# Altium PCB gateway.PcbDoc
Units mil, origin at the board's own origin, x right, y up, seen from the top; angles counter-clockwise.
Board outline 6000 x 4000 mil, 2 copper layers (Top Layer, Bottom Layer); 114 components, 94 nets, 405 pads, 209 vias.
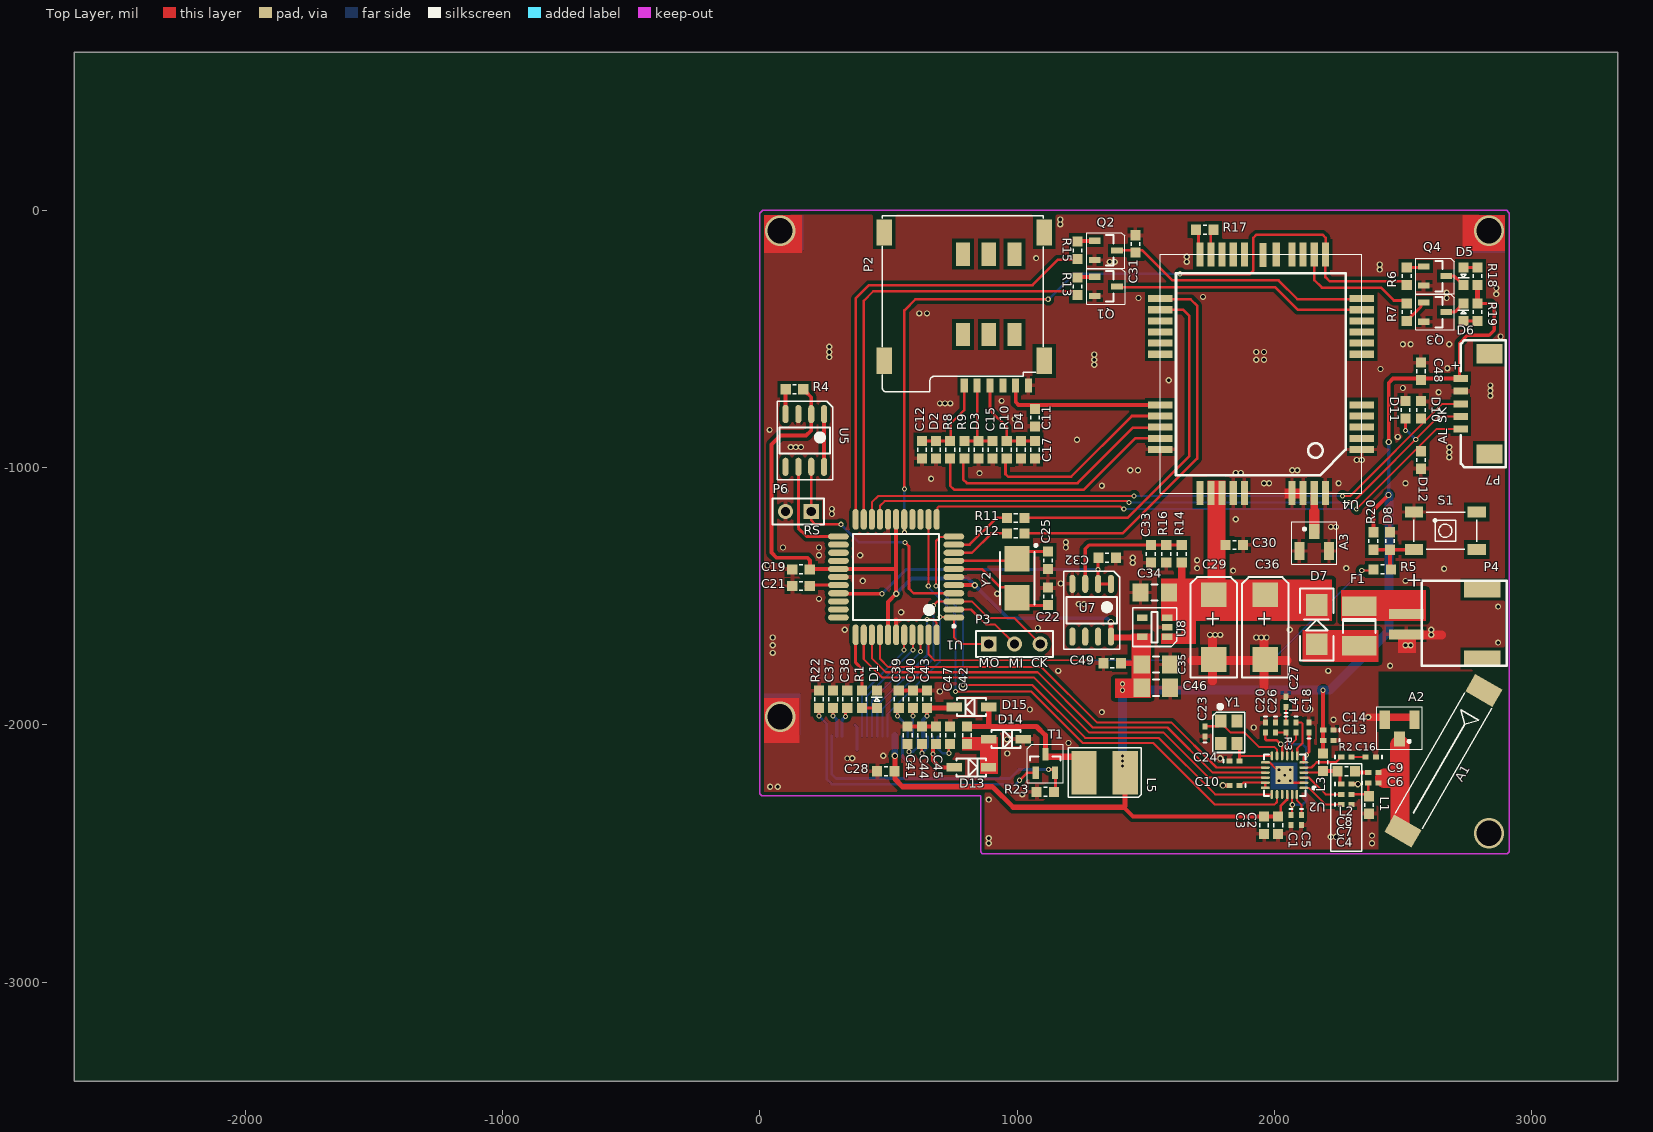
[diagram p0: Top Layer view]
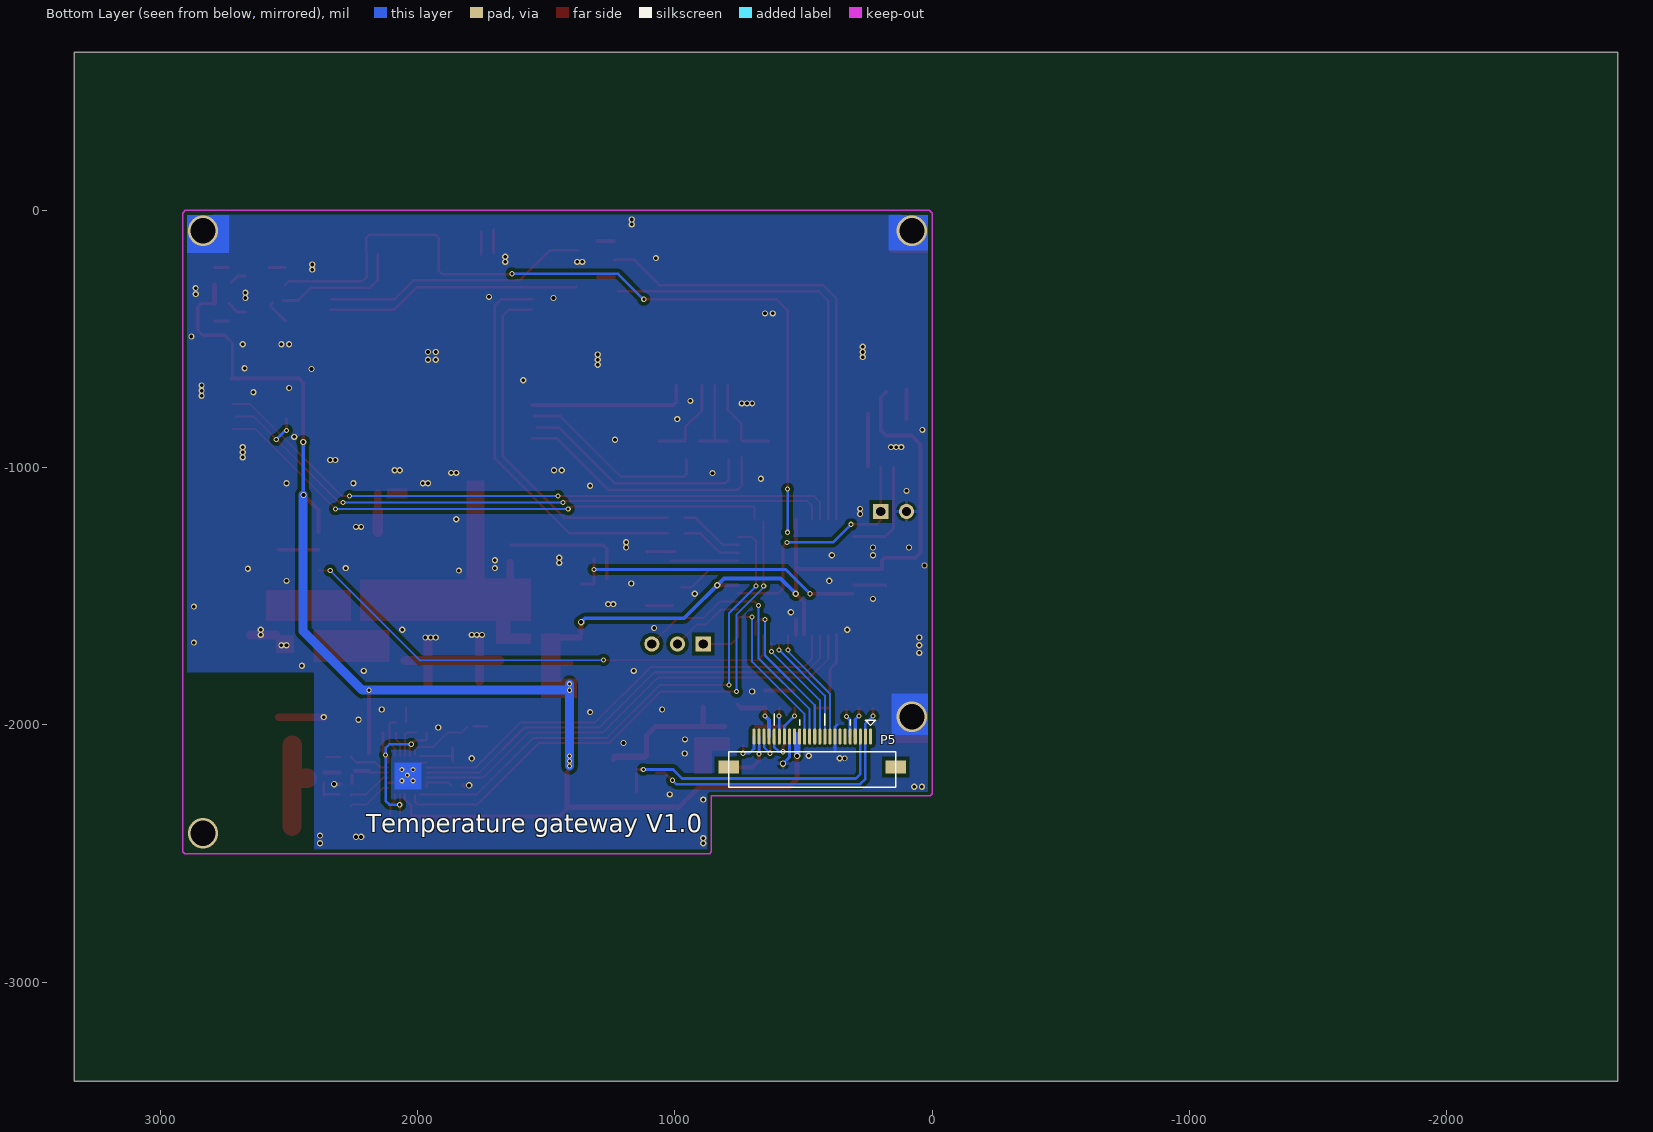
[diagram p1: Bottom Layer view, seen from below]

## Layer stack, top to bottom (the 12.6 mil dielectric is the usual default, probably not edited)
Top Layer: signal copper 1.4
Dielectric: dielectric 12.6, FR-4, Dk 4.8
Bottom Layer: signal copper 1.4

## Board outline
-2665,-3385 3335,-3385 3335,615 -2665,615

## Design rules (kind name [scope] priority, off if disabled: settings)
Clearance [All] p1 off: gap=12
ComponentClearance [All] p1 off: gap=10 collisioncheckmode=3 verticalgap=10
HoleSize [All] p1: absolutevalues=TRUE maxlimit=200 minlimit=1 maxpercent=80.000 minpercent=20.000
PolygonConnect [All] p1: connectstyle=Relief reliefconductorwidth=15 reliefentries=4 polygonreliefangle="90 Angle"
RoutingVias [All] p1: holewidth=28 width=50 viastyle="Through Hole" minholewidth=10 minwidth=20 maxholewidth=200 maxwidth=300
SolderMaskExpansion [All] p1: expansion=4
TestPointUsage [All] p1: valid=0 allowmultiple=FALSE
Testpoint [(IsPad And (OnTopLayer Or OnBottomLayer))] p1: side=3 testpointundercomponent=TRUE minsize=40 maxsize=100 preferedsize=60 minholesize=0 maxholesize=40 preferedholesize=32 testpointgrid=1 style=297 order=0123456789
Width [All] p1: maxlimit=200 minlimit=8 preferedwidth=10 toplayer_prefwidth=12 bottomlayer_prefwidth=12 minimp=50.000000 maximp=50.000000 favimp=50.000000
17 further rules are at their usual default settings.

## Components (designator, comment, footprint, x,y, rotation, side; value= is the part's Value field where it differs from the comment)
A1 "ANTA" ANTA-433 2500,-2412 r60 top
A2 "ANTA" IPEX 2487,-2008 r270 top
A3 "IPEX" IPEX 2155,-1295 r90 top
C1 "Cap" 0402-A 2065,-2370 r270 top
C2 "Cap" 0603 2015,-2390 r270 top
C3 "Cap" 0603 1960,-2390 r270 top
C4 "Cap" 0402-A 2280,-2310 r0 top
C5 "Cap" 0402-A 2105,-2370 r270 top
C6 "Cap" 0402-A 2385,-2225 r0 top
C7 "Cap" 0402-A 2280,-2270 r0 top
C8 "Cap" 0402-A 2280,-2230 r0 top
C9 "Cap" 0402-A 2385,-2185 r0 top
C10 "Cap" 0402-A 1845,-2235 r180 top
C11 "Cap" 0603 1070,-805 r90 top
C12 "Cap" 0603 630,-930 r90 top
C13 "Cap" 0402-A 2210,-2060 r180 top
C14 "Cap" 0402-A 2210,-2020 r180 top
C15 "Cap" 0603 905,-930 r270 top
C16 "Cap" 0402-A 2375,-2125 r180 top
C17 "Cap" 0603 1070,-930 r270 top
C18 "Cap" 0402-A 2135,-2010 r90 top
C19 "Cap" 0603 160,-1395 r180 top
C20 "Cap" 0402-A 1965,-2010 r270 top
C21 "Cap" 0603 160,-1460 r180 top
C22 "Cap" 0603 1120,-1500 r90 top
C23 "Cap" 0402-A 1730,-2025 r90 top
C24 "Cap" 0402-A 1845,-2140 r0 top
C25 "Cap" 0603 1120,-1360 r270 top
C26 "Cap" 0402-A 2005,-2010 r270 top
C27 "Cap" 0402-A 2045,-1910 r90 top
C28 "Cap" 0603 490,-2180 r0 top
C29 "Cap Pol3" C7343 1765,-1620 r270 top
C30 "Cap" 0603 1845,-1300 r180 top
C31 "Cap" 0603 1460,-130 r90 top
C32 "Cap" 0603 1350,-1350 r180 top
C33 "Cap" 0603 1520,-1335 r270 top
C34 "Cap" 3216[1206] 1535,-1485 r180 top
C35 "Cap" 3216[1206] 1540,-1765 r0 top
C36 "Cap Pol3" C7343 1965,-1620 r270 top
C37 "Cap" 0603 285,-1900 r270 top
C38 "Cap" 0603 340,-1900 r270 top
C39 "Cap" 0603 540,-1900 r270 top
C40 "Cap" 0603 595,-1900 r270 top
C41 "Cap" 0603 574.65,-2040 r270 top
C42 "Cap" 0603 805,-2040 r270 top
C43 "Cap" 0603 650,-1900 r270 top
C44 "Cap" 0603 630,-2040 r270 top
C45 "Cap" 0603 685,-2040 r270 top
C46 "Cap" 3216[1206] 1540,-1855 r0 top
C47 "Cap" 0603 740,-2040 r270 top
C48 "Cap" 0603 2570,-625 r270 top
C49 "Cap" 0603 1370,-1760 r180 top
D1 "TEST" 0603-LED 455,-1900 r90 top
D2 "RL0603E012M100K" 0603 685,-930 r270 top
D3 "RL0603E012M100K" 0603 850,-930 r270 top
D4 "RL0603E012M100K" 0603 1015,-930 r270 top
D5 "WORK" 0603-LED 2735,-255 r270 top
D6 "LINK" 0603-LED 2735,-395 r90 top
D7 "SS54" SMA 2165,-1610 r90 top
D8 "RL0603E012M100K" 0603 2450,-1285 r90 top
D10 "RL0603E012M100K" 0603 2570,-775 r90 top
D11 "RL0603E012M100K" 0603 2510,-775 r90 top
D12 "RL0603E012M100K" 0603 2570,-970 r270 top
D13 "MBR0503" SOD-123 755,-2165 r90 top
D14 "MBR0503" SOD-123 890,-2055 r90 top
D15 "MBR0503" SOD-123 890,-1930 r270 top
F1 "Fuse Thermal" 1812 2330,-1615 r270 top
L1 "Inductor" 0603 2368,-2311 r270 top
L2 "Inductor" 0603 2280,-2180 r0 top
L3 "Inductor" 0603 2190,-2145 r90 top
L4 "Inductor" 0402-A 2085,-2010 r270 top
L5 "Inductor" L-CD43 1340,-2185 r180 top
P2 "MircoSIM" "MICRO SIM" 990,-170 r180 top
P3 "Header 3" HDR1X3 890,-1685 r0 top
P4 "POW" HY2.0-2P 2513,-1569 r270 top
P5 "Header 24" FPC-24 240,-2045 r180 bottom locked
P6 "Header 2" HDR1X2 200,-1170 r180 top
P7 "TEMP" 1.25-5P 2725,-850 r90 top
Q1 "NPN" SOT-23-NPN 1345,-295 r270 top
Q2 "NPN" SOT-23-NPN 1345,-155 r270 top
Q3 "NPN" SOT-23-NPN 2625,-255 r270 top
Q4 "NPN" SOT-23-NPN 2625,-395 r270 top
R1 "Res1" 0603 397.48,-1900 r270 top
R2 "Res1" 0402-A 2280,-2125 r0 top
R3 "Res1" 0402-A 2045,-2010 r270 top
R4 "Res1" 0603 135,-695 r0 top
R5 "Res1" 0603 2420,-1395 r180 top
R6 "Res1" 0603 2515,-255 r90 top
R7 "Res1" 0603 2515,-395 r270 top
R8 "Res1" 0603 740,-930 r270 top
R9 "Res1" 0603 795,-930 r270 top
R10 "Res1" 0603 960,-930 r270 top
R11 "Res1" 0603 995,-1195 r180 top
R12 "Res1" 0603 995,-1255 r180 top
R13 "Res1" 0603 1235,-295 r270 top
R14 "Res1" 0603 1640,-1335 r270 top
R15 "Res1" 0603 1235,-155 r270 top
R16 "Res1" 0603 1580,-1335 r90 top
R17 "Res1" 0603 1730,-75 r0 top
R18 "Res1" 0603 2790,-255 r90 top
R19 "Res1" 0603 2790,-395 r270 top
R20 "Res1" 0603 2385,-1285 r270 top
R22 "Res1" 0603 230,-1900 r90 top
R23 "Res1" 0603 1110,-2260 r180 top
S1 "SW-PB" SW1 2665,-1245 r0 top
T1 "Si1304" SOT-23-NMOS 1110,-2150 r90 top
U1 "ATmega16" 44A_M 530,-1425 r180 top
U2 "A7139" QFN24N 2040,-2195 r180 top
U4 "G3524" G3524 1925,-870 r180 top
U5 "IMP706" SOIC8 175,-895 r270 top
U7 "LM358D" SOIC8 1290,-1555 r270 top
U8 "XC6219B30" SOT23-5N 1535,-1620 r180 top
Y1 "12.8M" XT3225 1855,-1985 r270 top
Y2 "XTAL" XT5032 1000,-1430 r270 top

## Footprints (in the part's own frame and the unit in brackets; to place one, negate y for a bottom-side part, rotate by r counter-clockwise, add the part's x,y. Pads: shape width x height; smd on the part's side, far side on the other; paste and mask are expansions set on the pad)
1.25-5P [mm]
  rect 1.9x2.6 smd: 0(-2.45,-2.835) 0(7.45,-2.835)
  rect 0.7x1.4 smd: 1(0,0) 2(1.25,0) 3(2.5,0) 4(3.75,0) 5(5,0)
  silkscreen extent -3.78,-4.44 8.79,0
44A_M [mm] "44-Pin Thin Quad Flat Pack 0.8 mm Pitch, IPC Low Density"
  oval 2.05x0.6 smd: 1(-5.7,4) 2(-5.7,3.2) 3(-5.7,2.4) 4(-5.7,1.6) 5(-5.7,0.8) 6(-5.7,0) 7(-5.7,-0.8) 8(-5.7,-1.6) 9(-5.7,-2.4) 10(-5.7,-3.2) 11(-5.7,-4) 23(5.7,-4) 24(5.7,-3.2) 25(5.7,-2.4) 26(5.7,-1.6) 27(5.7,-0.8) 28(5.7,0) 29(5.7,0.8) 30(5.7,1.6) 31(5.7,2.4) 32(5.7,3.2) 33(5.7,4)
  oval 0.6x2.05 smd: 12(-4,-5.7) 13(-3.2,-5.7) 14(-2.4,-5.7) 15(-1.6,-5.7) 16(-0.8,-5.7) 17(0,-5.7) 18(0.8,-5.7) 19(1.6,-5.7) 20(2.4,-5.7) 21(3.2,-5.7) 22(4,-5.7) 34(4,5.7) 35(3.2,5.7) 36(2.4,5.7) 37(1.6,5.7) 38(0.8,5.7) 39(0,5.7) 40(-0.8,5.7) 41(-1.6,5.7) 42(-2.4,5.7) 43(-3.2,5.7) 44(-4,5.7)
  silkscreen extent -5.82,-4.25 4.25,4.97, body extent -5,-5 5,5, height 1.2
0402-A [mm] "Chip Inductor; Body 1 x 0.5 mm (LxW typ)"
  rect 0.6x0.5 smd: 1(-0.5,0) 2(0.5,0)
  silkscreen extent -1.1,-0.15 -1.1,0.15
0603 [mm]
  rect 1x1 smd: 1(-0.864,0) 2(0.864,0)
  silkscreen extent -0.18,-0.43 0.18,0.43
0603-LED [mm]
  rect 1x1 smd: 1(-0.864,0) 2(0.864,0)
  silkscreen extent -0.18,-0.51 0.18,0.56
1812 [mm] "Chip Capacitor; Body 4.5 x 3.2 mm (LxW typ)"
  rect 1.9x3.4 smd: 1(-1.95,0) 2(1.95,0)
  silkscreen extent -0.7,-1.6 0.7,1.6
3216[1206] [mm] "Chip Resistor; Body 3.2 x 1.6 mm (LxW typ)"
  rect 1.6x1.8 smd: 1(-1.4,0) 2(1.4,0)
  silkscreen extent -0.3,-0.8 0.3,0.8
ANTA-433 [mm]
  rect 2x3.1 smd: 1(0,0) 2(16,0)
  silkscreen extent 1.14,-1.52 14.86,1.52
C7343 [mm] "Molded Capacitor, 2-Leads, Body 7.3x4.3mm, IPC Medium Density"
  rect 2.45x2.5 smd: 1(-3.2,0) 2(3.2,0)
  silkscreen extent -4.95,-2.29 4.95,2.29, body extent -3.75,-2.25 3.75,2.25, height 4.3
FPC-24 [mm]
  rect 2x1.3 smd: 0(-14,-3) 0(2.5,-3)
  oval 0.3x1.6 smd: 1(0,0) 2(-0.5,0) 3(-1,0) 4(-1.5,0) 5(-2,0) 6(-2.5,0) 7(-3,0) 8(-3.5,0) 9(-4,0) 10(-4.5,0) 11(-5,0) 12(-5.5,0) 13(-6,0) 14(-6.5,0) 15(-7,0) 16(-7.5,0) 17(-8,0) 18(-8.5,0) 19(-9,0) 20(-9.5,0) 21(-10,0) 22(-10.5,0) 23(-11,0) 24(-11.5,0)
  silkscreen extent -14,-5 2.5,2.23
G3524 [mm]
  rect 2.4x0.7 smd: 1(-10.55,1.5) 2(-10.55,0.4) 3(-10.55,-0.7) 4(-10.55,-1.8) 5(-10.55,-2.9) 6(-10.55,-7.9) 7(-10.55,-9) 8(-10.55,-10.1) 9(-10.55,-11.2) 10(-10.55,-12.3) 11(-10.55,-13.4) 21(9.35,-13.4) 22(9.35,-12.3) 23(9.35,-11.2) 24(9.35,-10.1) 25(9.35,-9) 26(9.35,-7.9) 27(9.35,-2.9) 28(9.35,-1.8) 29(9.35,-0.7) 30(9.35,0.4) 31(9.35,1.5)
  rect 0.7x2.4 smd: 12(-6.95,-17.75) 13(-5.85,-17.75) 14(-4.75,-17.75) 15(-3.65,-17.75) 16(1.05,-17.75) 17(2.15,-17.75) 18(3.25,-17.75) 19(4.35,-17.75) 20(5.45,-17.75) 32(5.45,5.8) 33(4.35,5.8) 34(3.25,5.8) 35(2.15,5.8) 36(1.05,5.8) 37(-3.65,5.8) 38(-4.75,5.8) 39(-5.85,5.8) 40(-6.95,5.8) 41(-2.1,-17.75) 42(-0.8,-17.7)
  silkscreen extent -10.55,-17.8 9.35,5.8
HDR1X2 [mm] "Connector; Header; 2 Position"
  rect 1.5x1.5 hole 0.9: 1(0,0)
  round 1.5 hole 0.9: 2(2.54,0)
  silkscreen extent -1.27,-1.27 3.81,1.27
HDR1X3 [mm] "Connector; Header; 3 Position"
  rect 1.5x1.5 hole 0.9: 1(0,0)
  round 1.5 hole 0.9: 2(2.54,0) 3(5.08,0)
  silkscreen extent -1.27,-1.27 6.35,1.27
HY2.0-2P [mm]
  rect 1.5x3.6 smd: 0(-2.413,7.493) 0(4.369,7.493)
  rect 1x3.4 smd: 1(0,0) 2(2,0)
  silkscreen extent -3.3,1.52 5.08,9.91
IPEX [mil] "SOT23, 3-Leads, Body 3.0x2.6mm (max), Pitch 0.95mm, IPC Medium Density"
  rect 59.06x41.34 smd: 1(46.5,-0.5)
  rect 70.87x39.37 smd: 2(-28.5,57.5) 3(-28.5,-57.5)
  silkscreen extent -80,-89 86,88
L-CD43 [mm]
  rect 2.5x4.3 smd: 1(-2.032,0) 2(2.032,0)
  silkscreen extent -3.61,-2.44 3.58,2.44
"MICRO SIM" [mm]
  rect 1.55x2.6 smd: 0(-2.95,10.53) 0(-2.95,-2.15) 0(12.85,10.53) 0(12.85,-2.15)
  rect 1.4x2.3 smd: 0(0,7.92) 0(0,0) 0(2.54,7.92) 0(2.54,0) 0(5.08,7.92) 0(5.08,0)
  rect 0.7x1.35 smd: 1(-0.12,12.955) 2(2.42,12.955) 3(4.96,12.955) 5(-1.39,12.955) 6(1.15,12.955) 7(3.69,12.955)
  silkscreen extent -2.82,-3.82 13.05,13.58
QFN24N [mm] "QFN, 24-Leads, Body 4.1x4.1mm (max), Pitch 0.50mm, IPC Medium Density"
  oval 0.889x0.25 smd: 1(-1.905,1.25) 2(-1.905,0.75) 3(-1.905,0.25) 4(-1.905,-0.25) 5(-1.905,-0.75) 6(-1.905,-1.25) 13(1.905,-1.25) 14(1.905,-0.75) 15(1.905,-0.25) 16(1.905,0.25) 17(1.905,0.75) 18(1.905,1.25)
  oval 0.25x0.889 smd: 7(-1.25,-1.905) 8(-0.75,-1.905) 9(-0.25,-1.905) 10(0.25,-1.905) 11(0.75,-1.905) 12(1.25,-1.905) 19(1.25,1.905) 20(0.75,1.905) 21(0.25,1.905) 22(-0.25,1.905) 23(-0.75,1.905) 24(-1.219,1.905)
  rect 1.8x1.8 smd: 25(0,0)
  silkscreen extent -3.03,-2.05 2.05,2.05, body extent -2.05,-2.05 2.05,2.05, height 0.8
SMA [mm] "Molded Diode, 2-Leads, Body 4.3x2.7mm, IPC Medium Density"
  rect 2.15x2.15 smd: 1(-1.93,0) 2(1.93,0)
  silkscreen extent -3.56,-1.65 3.56,1.65, body extent -2.28,-1.42 2.29,1.42, height 2.95
SOD-123 [mm]
  rect 0.85x1.524 smd: 1(0,0) 2(0,-3.4)
  silkscreen extent -0.9,-3.15 0.9,-0.25
SOIC8 [mm]
  oval 1.8x0.6 smd: 1(-2.625,1.905) 2(-2.625,0.635) 3(-2.625,-0.635) 4(-2.625,-1.905) 5(2.575,-1.905) 6(2.575,-0.635) 7(2.575,0.635) 8(2.575,1.905)
  silkscreen extent -3.89,-2.74 3.84,2.77, body extent -2.03,-2.5 1.97,2.5, height 1.76
SOT23-5N [mm]
  rect 1.05x0.65 smd: 1(-1.225,0.95) 2(-1.225,0) 3(-1.225,-0.95) 4(1.225,-0.95) 5(1.225,0.95)
  silkscreen extent -2.16,-1.91 2.16,1.91, body extent -0.87,-1.5 0.88,1.5, height 1.1
SOT-23-NMOS [mm] "SOT23, 3-Leads, Body 3.0x2.6mm (max), Pitch 0.95mm, IPC Medium Density"
  rect 1.25x0.6 smd: 1(-0.925,0.95) 2(0.925,0) 3(-0.925,-0.95)
  silkscreen extent -1.91,-1.78 1.91,1.78, body extent -0.7,-1.5 0.7,1.5, height 1.1
SOT-23-NPN [mm]
  rect 0.6x1.143 smd: 1(0.95,-1.108) 2(-0.95,-1.108) 3(0,1.108)
  silkscreen extent -1.75,-1.89 1.75,1.87, body extent -1.5,-0.66 1.5,0.74, height 1.1
SW1 [mm]
  rect 1.8x1.1 smd: 1(-3.1,1.85) 2(-3.1,-1.85) 3(3.1,-1.85) 4(3.1,1.85)
  silkscreen extent -3.1,-1.85 3.1,1.85
XT3225 [mm]
  rect 1.3x1.1 smd: 1(0,-1.6) 2(2.2,-1.6) 3(2.2,0) 4(0,0)
  silkscreen extent -1.6,-2.39 3.1,0.76
XT5032 [mm]
  rect 2.5x2.45 smd: 1(-1.925,0) 2(1.925,0)
  silkscreen extent -3.37,-1.7 2.6,1.97, body extent -2.58,-1.68 2.58,1.67, height 1.6

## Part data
A1 A2: library part SMB, "SMB Straight Connector"
C1 C2 C3 C4 C5 C6 C7 C8 C9 C10 C11 C12 C13 C14 C15 C16 C17 C18 C19 C20 C21 C22 C23 C24 C25 C26 C27 C28 C30 C31 C32 C33 C34 C35 C37 C38 C39 C40 C41 C42 C43 C44 C45 C46 C47 C48 C49: "Capacitor"
C29 C36: "Polarized Capacitor (Surface Mount)"
D1 D5 D6: library part LED2, "Typical RED, GREEN, YELLOW, AMBER GaAs LED"
D2 D3 D4 D8 D10 D11 D12: library part "Diode 18TQ045", "Schottky Rectifier"
D7 D13 D14 D15: library part "Diode 1N5408", "3 Amp Medium Power Silicon Rectifier Diode"
F1: "Thermal Fuse"
P3: "Header, 3-Pin"
P4: library part "Header 2", "Header, 2-Pin"
P5: "Header, 24-Pin"
P6: "Header, 2-Pin"
P7: library part "Header 5", "Header, 5-Pin"
Q1 Q2 Q3 Q4: library part 2N5551, "NPN General Purpose Amplifier"
R1 R2 R3 R4 R5 R6 R7 R8 R9 R10 R11 R12 R13 R14 R15 R16 R17 R18 R19 R20 R22 R23: "Resistor"
S1: "Switch"
T1: library part IRF644S, "HEXFET N-Channel Power MOSFET"
U1: library part ATmega16-16AI, "8-Bit AVR Microcontroller with 16K Bytes of In-System Programmable Flash Memory"
U5: library part MAX706RCSA, "+3V Voltage Monitoring, Low-Cost, 礟 Supervisory Circuit"
U7: "Dual Low-Power Operational Amplifier"
U8: library part LP5907
Y1: library part 3225-wy
Y2: "Crystal Oscillator"

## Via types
v1: diameter 24, hole 14, Top Layer to Bottom Layer, 131 vias
v2: diameter 20, hole 12, Top Layer to Bottom Layer, 49 vias
v3: diameter 25, hole 15, Top Layer to Bottom Layer, 12 vias
v4: diameter 20, hole 10, Top Layer to Bottom Layer, tented top, 5 vias
v5: diameter 118.11, hole 98.43, Top Layer to Bottom Layer, 4 vias
v6: diameter 24, hole 15, Top Layer to Bottom Layer, 3 vias
v7: diameter 25, hole 14, Top Layer to Bottom Layer, 1 vias
v8: diameter 22, hole 15, Top Layer to Bottom Layer, 1 vias
v9: diameter 25, hole 13, Top Layer to Bottom Layer, 1 vias
v10: diameter 26, hole 14, Top Layer to Bottom Layer, 1 vias
v11: diameter 26, hole 16, Top Layer to Bottom Layer, 1 vias

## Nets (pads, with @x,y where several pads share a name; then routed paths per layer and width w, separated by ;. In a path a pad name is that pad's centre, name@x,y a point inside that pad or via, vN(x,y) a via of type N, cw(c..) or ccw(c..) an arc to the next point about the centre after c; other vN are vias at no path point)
+3V: C2.1 C3.1 C13.2 C14.2 C19.1 C28.2 C35.1 C46.1 C48.2 C49.1 L3.2 L5.1 P5.15 P5.16 P7.5 R4.2 R18.1 R19.1 R20.1 U1.5 U1.17 U1.27 U1.38 U2.22 U5.2 U7.8 U8.5 | length 8567.6
  Top Layer w10: C2.1@2025,-2355 2025,-2315 2049.84,-2290.16 U2.22
  Top Layer w12: P7.5@2720,-650 2720,-515 2750,-485 2835,-485 2855,-465 2855,-375 2841,-361 R19.1
  Top Layer w15: R4.2@180,-706 200,-726 200,-855 180,-875 80,-875 45,-910 45,-1330 65,-1350 185,-1350 195,-1360 C19.1@195,-1390 ; C19.1@195.5,-1393.5 530,-1393.5 ; U1.38 498.5,-1521.5 v10(530,-1490) U1.17 ; U1.5 v9(835,-1456.5) ; 1420,-2290 1420,-2325 1451,-2356 C2.1 ; L3.2 v2(2190,-1865) ; R20.1 2385,-1165 v6(2444.37,-1105.63) ; v6(2445,-900) 2445,-670 2461.85,-653.15 P7.5
  Top Layer w20: v11(525,-2120) 525,-2210 555,-2240 905,-2240 985,-2320 1415,-2320 1420,-2315 L5.1 ; U7.8@1365,-1645 v3(1365,-1600) ; C49.1 C35.1@1460,-1760 ; R19.1 R18.1
  Top Layer w25: U7.8@1370,-1660 1465,-1660
  Bottom Layer w15: v10(530,-1490) 590,-1430 810,-1430 965,-1585 1350,-1585 v3(1365,-1600) ; v6@2445,-1105 v6(2445,-900)
  Bottom Layer w25: v11@525,-2115 525,-2040
  Bottom Layer w35: v2(1410,-2160) v2(1410,-1840) ; v2(1410,-1865) 2215,-1865 2445,-1635 v6@2445,-1105.63
  other v2: 1410,-2140 1410,-2120
+4.2V: C29.1 C30.2 C34.1 C36.1 D7.2 R14.2 U4.33 U4.34 U8.1 U8.3 | length 101
  Top Layer w30: 1640,-1470 R14.2
ALT_116: D12.1 P7.1 U1.12 | length 2211.3
  Top Layer w8: U1.12 690,-1198.07 690,-1155 695,-1150 1400,-1150 1410,-1160 v2(1415,-1160) ; v2(2320,-1160) 2630,-850 P7.1@2720,-850
  Bottom Layer w8: v2(1415,-1160) v2(2320,-1160)
D1: R1.1 U1.34 | length 226.9
  Top Layer w12: U1.34 372.52,-1757.52 397.48,-1782.48 R1.1
DOG: U1.23 U5.6 | length 407.7
  Top Layer w12: U5.6 150,-1235 182.52,-1267.52 U1.23
E_BUSY: P5.9 U1.40 | length 463.5
  Top Layer w8: v2(560,-1708.46) 560,-1650.91 U1.40
  Bottom Layer w8: P5.9 397.48,-1877.52 560,-1715 v2(560,-1708.46)
E_CLK: P3.3 P5.13 U1.3 | length 1078.7
  Top Layer w8: v2(675,-1535) 690,-1520 743.9,-1520 U1.3@748.9,-1525 ; U1.3 824.49,-1519.49 890,-1585 990,-1585 P3.3
  Bottom Layer w8: P5.13 476.22,-1938.78 675,-1740 v2(675,-1535)
E_CS: P5.12 U1.44 | length 624.7
  Top Layer w8: v2(650,-1590) 675,-1590 687.48,-1602.48 U1.44
  Bottom Layer w8: P5.12 456.54,-1923.46 650,-1730 v2(650,-1590)
E_D/C: P5.11 U1.42 | length 441.5
  Top Layer w8: v2(625,-1715) U1.42@625,-1681.42
  Bottom Layer w8: P5.11 436.85,-1903.15 v2(625,-1715)
E_RES: P5.10 U1.41 | length 432.8
  Top Layer w8: v2(595,-1708.46) U1.41@595,-1685.91
  Bottom Layer w8: P5.10 417.17,-1886.3 v2(595,-1708.46)
E_SDI: P3.1 P5.14 U1.1 | length 840.5
  Top Layer w8: v2(700,-1580) 746.89,-1580 751.89,-1585 U1.1 754.41,-1659.41 780,-1685 865,-1685 P3.1@890,-1660
  Bottom Layer w8: P5.14 495.91,-1959.09 700,-1755 v2(700,-1580)
GDR: P5.2 R22.1 T1.1 | length 1132.4
  Top Layer w10: v2(230,-1965) R22.1 ; v2(1010,-2215) 1038.58,-2186.42 T1.1
  Bottom Layer w10: v2@230,-1960 v2(230,-1965) 259.68,-1994.68 259.68,-2209.68 280,-2230 995,-2230 v2(1010,-2215)
GIO1: U1.11 U2.19 | length 2058.4
  Top Layer w8: v2(685,-1460) 685,-1285 700,-1270 U1.11@756.89,-1270 ; v2(790,-1845) 1060,-1845 1265,-2050 1550,-2050 1770,-2270 U2.19
  Bottom Layer w8: v2(685,-1460) 790,-1565 v2(790,-1845)
GIO2: U1.13 U2.20 | length 2170.1
  Top Layer w8: v2(655,-1460) U1.13@655,-1209.61 ; v2(760,-1870) 1055,-1870 1255,-2070 1530,-2070 1769.53,-2309.53 2000.47,-2309.53 2010.47,-2299.53 U2.20
  Bottom Layer w8: v2(655,-1460) 655,-1465 760,-1570 v2(760,-1870)
GND: A2.2 A2.3 A3.2 A3.3 C1.2 C2.2 C3.2 C4.2 C5.2 C8.2 C10.2 C11.1 C12.1 C13.1 C14.1 C15.2 C16.1 C17.2 C18.2 C19.2 C20.1 C21.2 C22.2 C23.1 C24.1 C25.2 C26.1 C27.2 C28.1 C29.2 C30.1 C31.2 C32.1 C33.2 C34.2 C35.2 C36.2 C37.1 C38.1 C39.1 C40.1 C41.1 C43.1 C44.1 C45.1 C46.2 C47.1 C48.1 C49.2 D1.2 D2.2 D3.2 D4.2 D8.2 D10.2 D11.2 D12.2 D14.2 L1.2 P2.5 P4.2 P5.8 P5.17 P6.2 P7.4 Q1.1 Q2.1 Q3.1 Q4.1 R16.1 R22.2 R23.2 S1.1 U1.6 U1.18 U1.28 U1.39 U2.2 U2.13 U2.25 U4.1 U4.31 U4.35 U4.36 U4.37 U4.38 U4.40 U5.3 U7.4 U8.2 | length 1660.3
  Top Layer w8: U2.13 1981.79,-2145.79 2006,-2170 U2.25@2010,-2170
  Top Layer w9: U2.25@2040.47,-2224.53 U2.2
  Top Layer w15: C41.1 C44.1 C45.1 ; v3(1800,-2235) C10.2 ; C8.2 v3(2325,-2230)
  Top Layer w16: U1.39 530,-1590 ; C39.1 C40.1 C43.1
  Top Layer w30: v1(2365,-1969.5) A2.2@2539.5,-1969.5
  Top Layer w35: 1680,-1750 2050,-1750 ; 1760,-1830 1760,-1670 ; 1960,-1850 1960,-1670 ; P4.2@2550,-1650 2650,-1650
  Bottom Layer w12: 370,-2000 377.8,-2007.8 377.8,-2097.2 ; P5.17 554.96,-2124.96 v3(580,-2150)
  other v1: 890,-2460 2380,-2460 890,-2440 2380,-2430 890,-2290 1020,-2270 40,-2240 70,-2240 480,-2120 1200,-2070 961,-2056 1920,-2010 2230,-1980 1330,-1950 1050,-1940 2140,-1940 1160,-1790 2210,-1790 2450,-1770 50,-1720 50,-1690 2510,-1690 2530,-1690 2870,-1680 50,-1660 1930,-1660 1950,-1660 1970,-1660 1750,-1650 1770,-1650 1790,-1650 1790,-1650 2610,-1650 330,-1630 2060,-1630 2610,-1630 1081,-1623 2870,-1540 1240,-1530 1260,-1530 230,-1510 1170,-1450 2510,-1440 1840,-1400 2660,-1393 1700,-1390 2280,-1390 30,-1380 1450,-1370 1700,-1360 1450,-1350 230,-1340 90,-1310 230,-1310 1190,-1310 1190,-1290 2220,-1230 2240,-1230 1850,-1200 280,-1180 280,-1160 100,-1090 1330,-1070 1960,-1060 1980,-1060 2250,-1060 2510,-1060 666,-1043 854,-1021 1850,-1020 1870,-1020 1440,-1010 1470,-1010 2070,-1010 2090,-1010 2320,-970 2340,-970 2680,-960 2680,-940 120,-920 140,-920 160,-920 2680,-920 1233,-891 2480,-880 38,-853 991,-811 700,-750 720,-750 740,-750 940,-740 2840,-720 2638.69,-706.47 2840,-700 2500,-690 2840,-680 1590,-660 2413,-616 2673,-613 1300,-600 1300,-580 1930,-580 1960,-580 270,-570 1300,-560 270,-550 1930,-550 1960,-550 270,-530 2500,-520 2530,-520 2680,-520 2880,-490 620,-400 650,-400 1472,-340 2670,-340 1723,-336 2863,-325 2670,-320 2863.57,-301.85 2410,-230 2410,-210 1360,-200 1380,-200 1660,-200 1074,-185 1660,-180 1168,-54 1168,-35
  other v3: 2220,-2435 2240,-2435 1790,-2130 700,-1870 549,-1562 923.23,-1490 400,-1440 390,-1340
  other v4: 2018.35,-2216.65 2061.65,-2216.65 2040,-2195 2018.35,-2173.35 2061.65,-2173.35
  other v5: 78.74,-1968.5 78.74,-78.74 2834.65,-78.74
  other v6: 962,-2111
  other v7: 360,-2130
  other v8: 340,-2130
GSM_PW: R13.2 U1.21 | length 1680.9
  Top Layer w10: U1.21 404.02,-350.98 441,-314 R13.2@1220,-314
GSM_RST: R15.2 U1.22 | length 1783.9
  Top Layer w10: U1.22 372.52,-342.48 425,-290 1060,-290 1158,-192 R15.2@1236,-192
GSM_RX: R12.2 U1.9 | length 237.9
  Top Layer w10: U1.9 824.49,-1330.51 900,-1255 R12.2
GSM_TX: R11.2 U1.10 | length 249.7
  Top Layer w10: U1.10 815.98,-1299.02 920,-1195 R11.2
HLT_CTL: P5.1
LINK_LED: Q4.2 R7.2 | length 93.9
  Top Layer w12: R7.2 2570,-374 2570,-365 Q4.2@2565,-360
MISO: P3.2 U1.2 | length 291.1
  Top Layer w8: U1.2 820.98,-1550.98 880,-1610 915,-1610 P3.2
NetA1_1: A1.1 A2.1 C6.2 C9.2 | length 382.3
  Top Layer w74.8: 2428.31,-2207 2488,-2207 A2.1@2488,-2078 ; 2473,-2207 2489,-2223 A1.1@2489,-2394
NetA3_1: A3.1 U4.39 | length 150.2
  Top Layer w30: 2155.31,-1170 U4.39
  Top Layer w40: 2155.31,-1170 2155.31,-1248.32 A3.1
NetC4_1: C4.1 U2.1 | length 174.6
  Top Layer w8: U2.1 2134.21,-2244.21 2200,-2310 2255.31,-2310 C4.1@2260.31,-2315
NetC5_1: C5.1 U2.24 | length 87.4
  Top Layer w8: U2.24 2088,-2293 2105,-2310 C5.1
NetC6_1: C6.1 C7.2 L1.1 | length 106.3
  Top Layer w10: C7.2@2304.69,-2270 L1.1@2361,-2270 ; L1.1@2365,-2275 C6.1@2365,-2225
NetC7_1: C7.1 U2.3 | length 174.4
  Top Layer w8: U2.3 2134.84,-2204.84 2200,-2270 2255.31,-2270 C7.1@2260.31,-2275
NetC8_1: C8.1 L2.1 L3.1 U2.4 | length 165.7
  Top Layer w8: U2.4 L3.1@2190,-2185.16
  Top Layer w12: C8.1@2255.31,-2230 L2.1@2255.31,-2194.32
  Top Layer w15: L3.1 L2.1@2245,-2179
NetC9_1: C9.1 L2.2 | length 61.3
  Top Layer w15: L2.2@2304,-2185 C9.1
NetC10_1: C10.1 U2.17 U2.18 | length 99.7
  Top Layer w8: C10.1@1869.69,-2235 1880.16,-2224.53 U2.17
NetC16_2: C16.2 R2.2 | length 55.6
  Top Layer w8: R2.2 C16.2
NetC21_1: C21.1 U1.29 | length 128
  Top Layer w10: C21.1@179,-1460 C21.1@182.5,-1456.5
  Top Layer w12: C21.1@182.5,-1456.5 U1.29
NetC22_1: C22.1 U1.7 Y2.2 | length 327.5
  Top Layer w10: U1.7@777.28,-1395 778.28,-1394 864,-1394 935,-1465 Y2.2@975,-1465
  Top Layer w12: Y2.2@1010,-1535 C22.1@1110,-1535
NetC23_2: C23.2 U2.11 Y1.1 | length 310.4
  Top Layer w8: Y1.1@1807.5,-2007.5 1830,-2030 1885,-2030 1940,-2085 2000,-2085 2010,-2095 U2.11@2010,-2114.29
  Top Layer w10: C23.2 Y1.1@1782.32,-2005.31
NetC24_2: C24.2 U2.12 Y1.3 | length 176.1
  Top Layer w8: 1864.69,-2120 U2.12
  Top Layer w10: C24.2 1864.69,-2120 Y1.3@1864.69,-2090
NetC25_1: C25.1 U1.8 Y2.1 | length 370
  Top Layer w10: U1.8@754,-1362 Y2.1@1014,-1362
  Top Layer w12: Y2.1@1000,-1325 C25.1@1110,-1325
NetC26_2: C26.2 R3.2 U2.9 | length 125.5
  Top Layer w8: C26.2 R3.2 ; U2.9 R3.2@2049.84,-2034.53
NetC27_1: C27.1 R3.1 | length 60.6
  Top Layer w8: R3.1 C27.1
NetC31_1: C31.1 Q2.3 U4.11 | length 1040.1
  Top Layer w10: Q2.3@1373.64,-155 1487,-155 1604,-272 2017,-272 2090,-345 U4.11@2335,-345
NetC33_1: C33.1 R14.1 R16.2 U7.3 | length 497.4
  Top Layer w12: U7.3@1265,-1431.64 1265,-1315 1279,-1301 C33.1 R16.2 R14.1
NetC39_2: C39.2 P5.18 | length 127.4
  Top Layer w10: v2(535,-1965) C39.2@535,-1934
  Bottom Layer w10: v2(535,-1965) 574.65,-2004.65 P5.18
NetC42_1: C42.1 D15.1 L5.2 T1.2 | length 604.7
  Top Layer w20: C42.1 1076,-2006 1110,-2040 T1.2@1110,-2120 ; 890,-2000 D15.1 ; L5.2@1226.42,-2120 L5.2@1240,-2133.58
  Top Layer w25: T1.2@1119.58,-2123 L5.2@1236,-2123
NetC42_2: C42.2 D13.2 D14.1
NetD1_1: D1.1 R1.2 | length 57.5
  Top Layer w10: R1.2 D1.1
NetD5_1: D5.1 R18.2 | length 55
  Top Layer w12: D5.1 R18.2
NetD5_2: D5.2 Q3.3 | length 66.7
  Top Layer w12: Q3.3 2700,-255 D5.2@2725,-280
NetD6_1: D6.1 R19.2 | length 55
  Top Layer w12: D6.1 R19.2
NetD6_2: D6.2 Q4.3 | length 80.4
  Top Layer w12: Q4.3 2701,-395 D6.2
NetD7_1: D7.1 F1.2
NetD8_1: D8.1 R5.1 R20.2 S1.2 | length 230.4
  Top Layer w8: S1.2@2541.79,-1319 S1.2
  Top Layer w15: R20.2 D8.1 ; R5.1@2450,-1391 D8.1 ; S1.2@2541.79,-1319 D8.1
NetL4_1: L4.1 U2.7 | length 160.6
  Top Layer w8: L4.1 2105.31,-1990.32 2110,-1995 2110,-2070 2089.21,-2090.79 U2.7
NetL4_2: L4.2 U2.8 | length 96.7
  Top Layer w8: U2.8 2069.53,-2070.47 2085,-2055 L4.2
NetQ1_2: Q1.2 R13.1 | length 63
  Top Layer w15: R13.1@1237,-258 Q1.2@1299.96,-258
NetQ1_3: Q1.3 U4.10 | length 994.9
  Top Layer w10: Q1.3@1383,-295 1387,-299 2004,-299 2090.75,-385.75 U4.10
NetQ2_2: Q2.2 R15.1 | length 63
  Top Layer w15: R15.1@1238.04,-119 Q2.2@1301,-119
NetR2_1: R2.1 U2.5 | length 163.5
  Top Layer w8: U2.5 2144.53,-2165.47 2165,-2145 2240,-2145 2257.66,-2127.34 R2.1@2257.66,-2122.34
NetR4_1: R4.1 U5.4 | length 116.4
  Top Layer w15: U5.4@100,-811.36 R4.1@100,-695
NetR7_1: R7.1 U4.13 | length 501.8
  Top Layer w10: U4.13 2155.31,-270.31 2185,-300 2415,-300 2465,-350 R7.1@2525,-350
NetR8_2: R8.2 U4.30 | length 1015.1
  Top Layer w10: R8.2@740,-960 740,-1070 755,-1085 1260,-1085 1460,-885 U4.30@1556,-885
NetR9_2: R9.2 U4.29 | length 918.7
  Top Layer w10: R9.2@790,-970 790,-1045 805,-1060 1235,-1060 1451,-844 U4.29@1538,-844
NetR10_2: R10.2 U4.28 | length 747.9
  Top Layer w10: R10.2@955,-970 955,-1025 965,-1035 1210,-1035 1446,-799 U4.28@1546,-799
NetR11_1: R11.1 U4.22 | length 1408.6
  Top Layer w10: R11.1 1430,-1195 1670,-955 1670,-410 1645.75,-385.75 U4.22
NetR12_1: R12.1 U4.21 | length 1540.6
  Top Layer w10: R12.1 1410,-1255 1700,-965 1700,-370 1675,-345 1559.45,-345 U4.21
NetR17_1: R17.1 U4.20 | length 92.2
  Top Layer w10: U4.20@1705.43,-166.18 R17.1@1705.43,-74
NetU5_1: U5.1 U5.8 | length 204.7
  Top Layer w15: U5.8 U5.1
PREVGH: C43.2 D15.2 P5.21 | length 229.7
  Top Layer w15: v2(650,-1965) C43.2 ; D15.2@742.14,-1934 D15.2@756.14,-1920
  Top Layer w20: C43.2 D15.2@742.14,-1934
  Bottom Layer w15: P5.21 633.7,-1981.3 v2(650,-1965)
PREVGL: C45.2 D13.1 P5.23 | length 208.3
  Top Layer w15: C45.2@673.07,-2085.93 673.07,-2138.07 700,-2165 D13.1@750,-2165
  Bottom Layer w10: v2(673.07,-2113.07) P5.23
RESE: P5.3 R23.1 T1.3 | length 1110
  Top Layer w10: v2@1122,-2173 T1.3@1147.4,-2173
  Top Layer w12: R23.1@1149,-2260 T1.3@1149,-2189.82
  Bottom Layer w10: P5.3@279,-2043 279.02,-2045 279.37,-2083 279.37,-2191.37 296,-2208 972,-2208 1007,-2173 v2@1124,-2173
  other v2: 1123,-2173
RST: P6.1 U1.4 U5.7 | length 973.2
  Top Layer w10: U5.7 200,-1205 215,-1220 v2(315,-1220) ; v2@565.5,-1291.5 580,-1306 580,-1470 597.99,-1487.99 U1.4
  Bottom Layer w10: v2(315,-1220) 385,-1290 v2@563,-1290
  other v2: 564,-1290
SCK_116: D11.1 P7.2 U1.19 | length 2545.6
  Top Layer w8: U1.19 467.01,-1147.99 485,-1130 1425,-1130 v2(1435,-1135) ; v2(2290,-1135) 2305,-1135 2640,-800 2705,-800 P7.2@2710,-805
  Top Layer w12: v2(2510,-855) D11.1
  Bottom Layer w8: v2(1435,-1135) v2(2290,-1135) ; v2(2510,-855) v2@2515,-855
  Bottom Layer w12: v2@2515,-855 v2(2550,-890)
SCK_7139: U1.36 U2.15 | length 1804.8
  Top Layer w8: U1.36 435.51,-1740.51 490,-1795 1080,-1795 1295,-2010 1585,-2010 1760.16,-2185.16 U2.15
SCS_7139: U1.37 U2.14 | length 1766
  Top Layer w8: U1.37 467.01,-1742.01 500,-1775 1095,-1775 1310,-1990 1600,-1990 1775.47,-2165.47 U2.14
SDA_116: D10.1 P7.3 U1.20 | length 2509.2
  Top Layer w8: U1.20 435.51,-1134.49 460,-1110 v2(1455,-1110) ; v2(2265,-1110) 2295,-1110 2653.43,-751.57 P7.3@2720,-751.57
  Bottom Layer w8: v2(1455,-1110) v2(2265,-1110)
SDA_7139: U1.35 U2.16 | length 1846.5
  Top Layer w8: U1.35 404.02,-1744.02 475,-1815 1065,-1815 1280,-2030 1570,-2030 1744.84,-2204.84 U2.16
SIM_CLK: C12.2 D2.1 P2.3 R8.1 | length 338.8
  Top Layer w10: R8.1@742,-893 742,-829 794.72,-776.28 P2.3
  Top Layer w12: C12.2@636,-896 R8.1
SIM_DAT: C15.1 D3.1 P2.7 R9.1 | length 321.1
  Top Layer w10: D3.1@844.72,-890.72 P2.7
  Top Layer w12: R9.1 D3.1 904,-896 C15.1@905,-895
SIM_RST: C17.1 D4.1 P2.2 R10.1 | length 346
  Top Layer w10: P2.2 894.72,-776.72 960,-842 R10.1@960,-895
  Top Layer w12: R10.1 C17.1@1064,-896
STAT: R6.1 U1.16 U4.12 | length 3205
  Top Layer w10: U1.16@561.5,-1223 561.5,-1251 v2(562,-1251) ; v2(562,-1083) 562,-388 605,-345 v2@1123,-345 ; v2@1636,-248 1904,-248 1919,-233 1919,-106 1931,-94 2187,-94 2200,-107 U4.12@2200,-162 ; U4.12 2198.62,-258.62 2215,-275 2501,-275 R6.1
  Bottom Layer w10: v2@562,-1252 v2@562,-1081 ; v2@1121.5,-345.5 1221,-246 v2@1633,-246
  other v2: 1121,-345 1634,-246
SW1: R5.2 U1.43 | length 1956.5
  Top Layer w8: U1.43 655.98,-1725.98 680,-1750 v2(1277.59,-1746.94) ; v2(2340,-1400) R5.2@2381,-1400
  Bottom Layer w8: v2(1277.59,-1746.94) 1990,-1750 v2(2340,-1400)
TSCL: P5.6
TSDA: P5.7
VCOM: C47.2 P5.24 | length 127.6
  Top Layer w10: v2(735,-2110) C47.2@735,-2079
  Bottom Layer w10: P5.24 692.76,-2091.81 710.94,-2110 v2(735,-2110)
VDA: C1.1 C18.1 C20.2 U2.6 U2.10 U2.23 | length 713.3
  Top Layer w8: C1.1@2069.53,-2345.79 U2.23
  Top Layer w10: C20.2 1965,-2055 1970,-2060 2010,-2060 2030.16,-2080.16 U2.10 ; U2.6 2115,-2125 2135,-2105 C18.1
  Bottom Layer w10: v2(2025,-2075) 2110,-2075 2125,-2090 2125,-2295 2110,-2310 v2(2070,-2310)
  other v2: 2125,-2116.27
VDD3.0: R17.2 U4.19 | length 89.2
  Top Layer w10: U4.19 R17.2@1753.74,-82
VGH: C38.2 P5.5 | length 109.2
  Top Layer w12: v2(332.5,-1967.5) C38.2@332.5,-1941.5
  Bottom Layer w12: P5.5 318.74,-1981.26 v2(332.5,-1967.5)
VGL: C37.2 P5.4 | length 116.8
  Top Layer w12: v2(285,-1965) C37.2
  Bottom Layer w12: v2(285,-1965) 299.06,-1979.06 P5.4
VIN: F1.1 P4.1
VPP: C40.2 P5.19 | length 111.3
  Top Layer w10: v2(595,-1965) C40.2
  Bottom Layer w10: P5.19 595,-2044.33 v2(595,-1965)
VSA: C32.2 U1.30 U7.1 U7.2 | length 1197.4
  Top Layer w12: U1.30@307.6,-1490 v2(475,-1490) ; C32.2@1315,-1351 v2(1315,-1395) U7.2 U7.1
  Bottom Layer w12: v2(475,-1490) 570,-1395 v2(1315,-1395)
VSH: C41.2 P5.20 | length 116.7
  Top Layer w10: C41.2@570,-2074 580,-2084 v2(580,-2104.06)
  Bottom Layer w10: v2(580,-2104.06) 595.97,-2104.06 614.02,-2086.01 P5.20
VSIM: C11.2 P2.1 U4.27 | length 631.4
  Top Layer w15: P2.1 994.72,-744.72 1005.83,-755.83 U4.27
VSL: C44.2 P5.22 | length 104.7
  Top Layer w10: v2(630,-2110) C44.2@630,-2080
  Bottom Layer w10: v2(630,-2110) 653.39,-2086.61 P5.22
WORK_LED: Q3.2 R6.2 | length 63
  Top Layer w12: R6.2 Q3.2@2577.96,-221
pads on no net: A1.2 P2.0 P2.6 P4.0 P5.0 P7.0 S1.3 S1.4 U1.14 U1.15 U1.24 U1.25 U1.26 U1.31 U1.32 U1.33 U2.21 U4.2 U4.3 U4.4 U4.5 U4.6 U4.7 U4.8 U4.9 U4.14 U4.15 U4.16 U4.17 U4.18 U4.23 U4.24 U4.25 U4.26 U4.32 U4.41 U4.42 U5.5 U7.5 U7.6 U7.7 U8.4 Y1.2 Y1.4
copper on no net:
  other v5: 2834.65,-2421.26

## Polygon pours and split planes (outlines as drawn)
GND on Top Layer "GND_L01_P004" (solid, remove dead copper, pour order 4): -431,217 -425,223 3124,223 3124,-2808 3155,-2839 2871,-2555 -264,-2555
GND on Bottom Layer "Bottom Layer-No Net" (solid, remove dead copper): 265,-2045 750,-2045 750,-2185 765,-2200 735,-2230 260,-2230
GND on Bottom Layer "GND_L02_P006" (solid, remove dead copper, pour order 6): -548,242 3099,242 3155,186 3069,100 3069,-2826 -43,-2826 -326,-2543

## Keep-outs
Keep-Out Layer:
  lines w5: 0,-2268 7.59,-2275.59 858,-2275.59 858,-2493 865,-2500 2906,-2500 2913.39,-2492.61 2913.39,-10.39 2903,0 11,0 0,-11 0,-2268

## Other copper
Top Layer:
  rectangle net GND: 2040,-1120 2120,-1080
  rectangle net GND: 2480,-1720 2550,-1650
  rectangle net GND: 2732,-158 2896,-17
  rectangle net GND: 17,-166 164,-17
  rectangle net GND: 16.82,-2070 155,-1895.31
  rectangle net NetC10_1: 1959.29,-2245 1970,-2220
  rectangle net +3V: 1445,-1895 1520,-1645
  rectangle net +4.2V: 1560,-1685 1675,-1645
  rectangle net +4.2V: 1640,-1685 1695,-1590
  rectangle net +4.2V: 1560,-1595 1745,-1430
  rectangle net VIN: 2260,-1595 2590,-1475
  rectangle net NetD7_1: 2110,-1755 2405,-1630
  rectangle net +4.2V: 1695,-1595 2225,-1435
  rectangle net +4.2V: 1740,-1510 1810,-1050
  rectangle net NetC42_2: 785,-2100 925,-2047
  rectangle net NetC42_2: 855,-2190 925,-2050
  rectangle net +3V: 1380,-1895 1510,-1820
  pour cut-out: 2404,-1792 2909,-1792 2909,-2497 2907,-2499 2404,-2499
Bottom Layer:
  rectangle net GND: 2734,-166 2897,-17
  rectangle net GND: 17,-156 169,-17
  rectangle net GND: 16.82,-2039 158,-1877.52
  rectangle net GND: 1985,-2250 2090,-2145
  pour cut-out: 2908,-1795 2403,-1795 2403,-2500 2405,-2502 2908,-2502

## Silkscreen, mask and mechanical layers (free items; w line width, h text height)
Top Overlay:
  lines w5: 2220,-2490 2340,-2490 2340,-2150 2220,-2150 2220,-2490
  text "+" at 2683.44,-631.23 h60
  text "SK" at 2683,-828 h60 r90
  text "AL" at 2684,-908 h60 r90
  text "RS" at 170,-1272 h60
  text "+" at 2511,-1482 h100
  text "MO" at 851,-1788 h60
  text "CK" at 1055,-1788 h60
  text "MI" at 968,-1789 h60
Bottom Overlay:
  text "Temperature gateway V1.0" at 2200,-2440 h120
